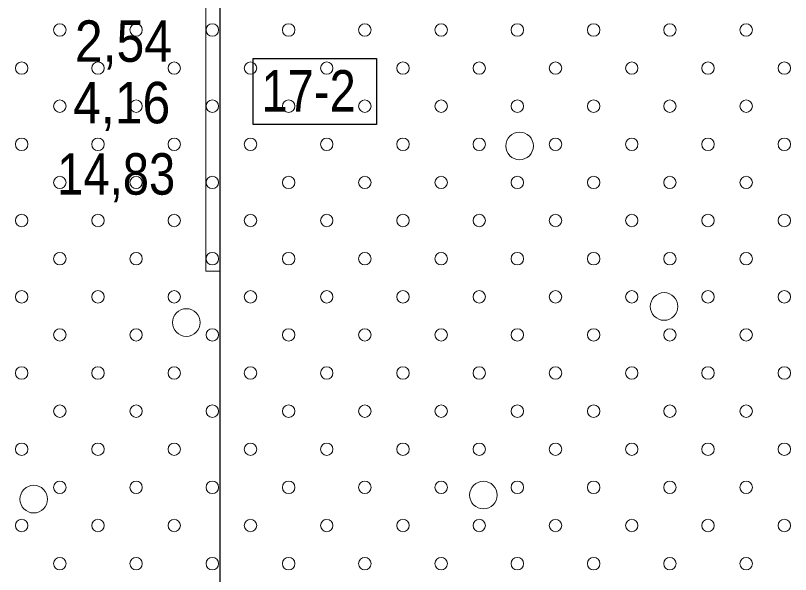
# Model space of a CAD drawing. Extents: x 640121 to 640955, y 6441885 to 6442246.
# Drawn here: x 640364 to 640420.1, y 6442136.1 to 6442176.5 of the extents above; entities that cross this region are included whole.
import ezdxf
from ezdxf.enums import TextEntityAlignment as Align

# ---------------------------------------------------------------- set-up
doc = ezdxf.new("R2010")
doc.units = 0
doc.header["$LTSCALE"] = 1.2
for name, color, linetype, lineweight in [('32', 7, 'Continuous', 13), ('33', 7, 'Continuous', 13), ('42', 7, 'Continuous', 13), ('47', 7, 'Continuous', 13)]:
    doc.layers.add(name, color=color, linetype=linetype, lineweight=lineweight)

msp = doc.modelspace()

# ---------------------------------------------------------------- linework, layer by layer
at = {"layer": '32', "lineweight": 25}
msp.add_line((640378.77, 6442207.95), (640378.77, 6442118.83), dxfattribs=at)
at = {"layer": '33'}
msp.add_lwpolyline([(640377.77, 6442182.83), (640377.77, 6442158), (640378.77, 6442158), (640378.77, 6442182.98)], close=True, dxfattribs=at)
at = {"layer": '33', "lineweight": 25}
msp.add_lwpolyline([(640381.18, 6442173.39), (640390.1, 6442173.39), (640390.1, 6442168.61), (640381.18, 6442168.61)], close=True, dxfattribs=at)
at = {"layer": '42'}
for centre in [(640367.208, 6442175.455), (640372.723, 6442175.455), (640378.239, 6442175.455), (640383.754, 6442175.455), (640389.27, 6442175.455), (640394.785, 6442175.455), (640400.301, 6442175.455), (640405.816, 6442175.455), (640411.332, 6442175.455), (640416.847, 6442175.455), (640364.45, 6442172.697), (640369.966, 6442172.697), (640375.481, 6442172.697), (640380.997, 6442172.697), (640386.512, 6442172.697), (640392.027, 6442172.697), (640397.543, 6442172.697), (640403.058, 6442172.697), (640408.574, 6442172.697), (640414.089, 6442172.697), (640419.605, 6442172.697), (640367.208, 6442169.94), (640372.723, 6442169.94), (640378.239, 6442169.94), (640383.754, 6442169.94), (640389.27, 6442169.94), (640394.785, 6442169.94), (640400.301, 6442169.94), (640405.816, 6442169.94), (640411.332, 6442169.94), (640416.847, 6442169.94), (640364.45, 6442167.182), (640369.966, 6442167.182), (640375.481, 6442167.182), (640380.997, 6442167.182), (640386.512, 6442167.182), (640392.027, 6442167.182), (640397.543, 6442167.182), (640403.058, 6442167.182), (640408.574, 6442167.182), (640414.089, 6442167.182), (640419.605, 6442167.182), (640367.208, 6442164.424), (640372.723, 6442164.424), (640378.239, 6442164.424), (640383.754, 6442164.424), (640389.27, 6442164.424), (640394.785, 6442164.424), (640400.301, 6442164.424), (640405.816, 6442164.424), (640411.332, 6442164.424), (640416.847, 6442164.424), (640364.45, 6442161.667), (640369.966, 6442161.667), (640375.481, 6442161.667), (640380.997, 6442161.667), (640386.512, 6442161.667), (640392.027, 6442161.667), (640397.543, 6442161.667), (640403.058, 6442161.667), (640408.574, 6442161.667), (640414.089, 6442161.667), (640419.605, 6442161.667), (640367.208, 6442158.909), (640372.723, 6442158.909), (640378.239, 6442158.909), (640383.754, 6442158.909), (640389.27, 6442158.909), (640394.785, 6442158.909), (640400.301, 6442158.909), (640405.816, 6442158.909), (640411.332, 6442158.909), (640416.847, 6442158.909), (640364.45, 6442156.151), (640369.966, 6442156.151), (640375.481, 6442156.151), (640380.997, 6442156.151), (640386.512, 6442156.151), (640392.027, 6442156.151), (640397.543, 6442156.151), (640403.058, 6442156.151), (640408.574, 6442156.151), (640414.089, 6442156.151), (640419.605, 6442156.151), (640367.208, 6442153.393), (640372.723, 6442153.393), (640378.239, 6442153.393), (640383.754, 6442153.393), (640389.27, 6442153.393), (640394.785, 6442153.393), (640400.301, 6442153.393), (640405.816, 6442153.393), (640411.332, 6442153.393), (640416.847, 6442153.393), (640364.45, 6442150.636), (640369.966, 6442150.636), (640375.481, 6442150.636), (640380.997, 6442150.636), (640386.512, 6442150.636), (640392.027, 6442150.636), (640397.543, 6442150.636), (640403.058, 6442150.636), (640408.574, 6442150.636), (640414.089, 6442150.636), (640419.605, 6442150.636), (640367.208, 6442147.878), (640372.723, 6442147.878), (640378.239, 6442147.878), (640383.754, 6442147.878), (640389.27, 6442147.878), (640394.785, 6442147.878), (640400.301, 6442147.878), (640405.816, 6442147.878), (640411.332, 6442147.878), (640416.847, 6442147.878), (640364.45, 6442145.12), (640369.966, 6442145.12), (640375.481, 6442145.12), (640380.997, 6442145.12), (640386.512, 6442145.12), (640392.027, 6442145.12), (640397.543, 6442145.12), (640403.058, 6442145.12), (640408.574, 6442145.12), (640414.089, 6442145.12), (640419.605, 6442145.12), (640367.208, 6442142.363), (640372.723, 6442142.363), (640378.239, 6442142.363), (640383.754, 6442142.363), (640389.27, 6442142.363), (640394.785, 6442142.363), (640400.301, 6442142.363), (640405.816, 6442142.363), (640411.332, 6442142.363), (640416.847, 6442142.363), (640364.45, 6442139.605), (640369.966, 6442139.605), (640375.481, 6442139.605), (640380.997, 6442139.605), (640386.512, 6442139.605), (640392.027, 6442139.605), (640397.543, 6442139.605), (640403.058, 6442139.605), (640408.574, 6442139.605), (640414.089, 6442139.605), (640419.605, 6442139.605), (640367.208, 6442136.847), (640372.723, 6442136.847), (640378.239, 6442136.847), (640383.754, 6442136.847), (640389.27, 6442136.847), (640394.785, 6442136.847), (640400.301, 6442136.847), (640405.816, 6442136.847), (640411.332, 6442136.847), (640416.847, 6442136.847)]:
    msp.add_circle(centre, 0.45, dxfattribs=at)
at = {"layer": '47'}
for centre in [(640400.458, 6442167.066), (640410.912, 6442155.451), (640376.356, 6442154.289), (640397.844, 6442141.802), (640365.321, 6442141.512)]:
    msp.add_circle(centre, 1, dxfattribs=at)

# ---------------------------------------------------------------- texts
at = {"layer": '32'}
for s, width, p in [('2,54', 0.9, (640371.81, 6442173.15)), ('14,83', 0.85, (640371.285, 6442163.54))]:
    msp.add_text(s, height=3, dxfattribs=dict(at, width=width)).set_placement(p, align=Align.CENTER)
at = {"layer": '33'}
for s, width, p in [('17-2', 0.85, (640385.2, 6442169.55)), ('4,16', 0.9, (640371.68, 6442168.7))]:
    msp.add_text(s, height=3, dxfattribs=dict(at, width=width)).set_placement(p, align=Align.CENTER)

doc.saveas('drawing.dxf')
